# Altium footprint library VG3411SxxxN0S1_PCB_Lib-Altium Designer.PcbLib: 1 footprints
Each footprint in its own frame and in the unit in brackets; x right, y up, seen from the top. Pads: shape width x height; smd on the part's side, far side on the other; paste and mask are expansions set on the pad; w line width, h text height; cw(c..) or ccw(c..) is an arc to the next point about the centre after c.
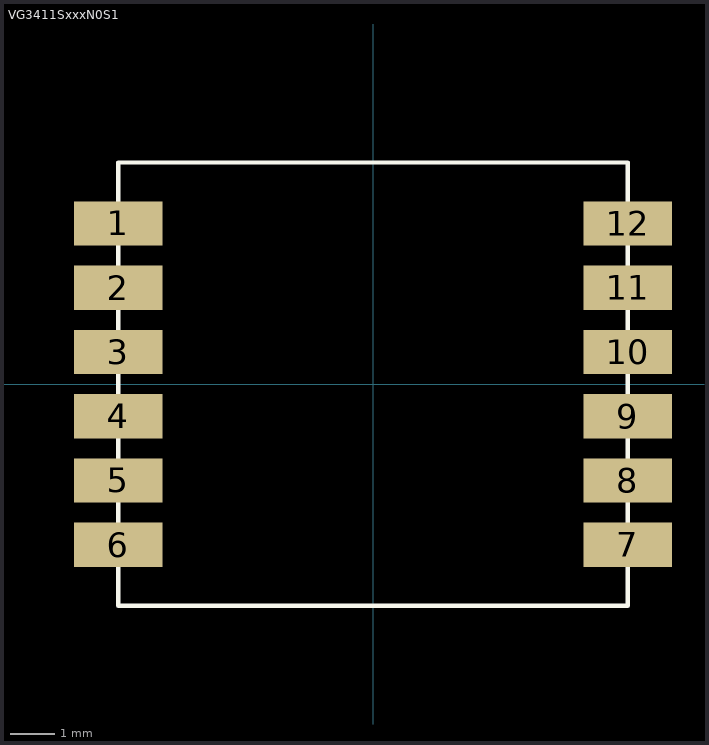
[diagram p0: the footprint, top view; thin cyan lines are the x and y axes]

## VG3411SxxxN0S1 [mm]
pads (13):
  round 1 on Top Overlay: 1(-7.112,4.953)
  rect 2x1 smd: 1(-5.75,3.625) 2(-5.75,2.175) 3(-5.75,0.725) 4(-5.75,-0.725) 5(-5.75,-2.175) 6(-5.75,-3.625) 7(5.75,-3.625) 8(5.75,-2.175) 9(5.75,-0.725) 10(5.75,0.725) 11(5.75,2.175) 12(5.75,3.625)
Top Overlay:
  lines w0.1: -5.75,-5 -5.75,5 5.75,5 5.75,-5 -5.75,-5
